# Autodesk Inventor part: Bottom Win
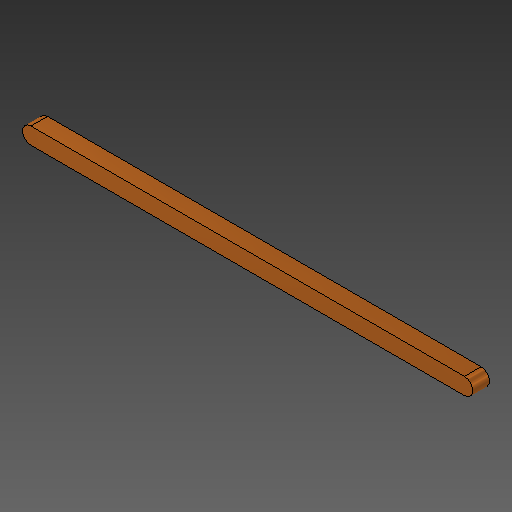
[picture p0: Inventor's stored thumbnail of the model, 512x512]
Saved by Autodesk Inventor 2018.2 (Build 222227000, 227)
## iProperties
Created: 2018-03
Part Number: Bottom Win
Material: Gold
Document SubType Name: Modeling
Designer: PeterMaxwell-Stewart
Mass: 64.6198 g
Surface Area: 27.1781 cm^2
Volume: 3.34817 cm^3
Density: 19.3 g/cm^3
Appearance: Metal 1600F Hot
Author: PeterMaxwell-Stewart
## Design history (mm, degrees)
derived "O's and X's.ipt"
feature "Bottom Win::O's and X's.ipt" dims "d0" = 10
tag "TaggingFeature1"
body "Solid1"
